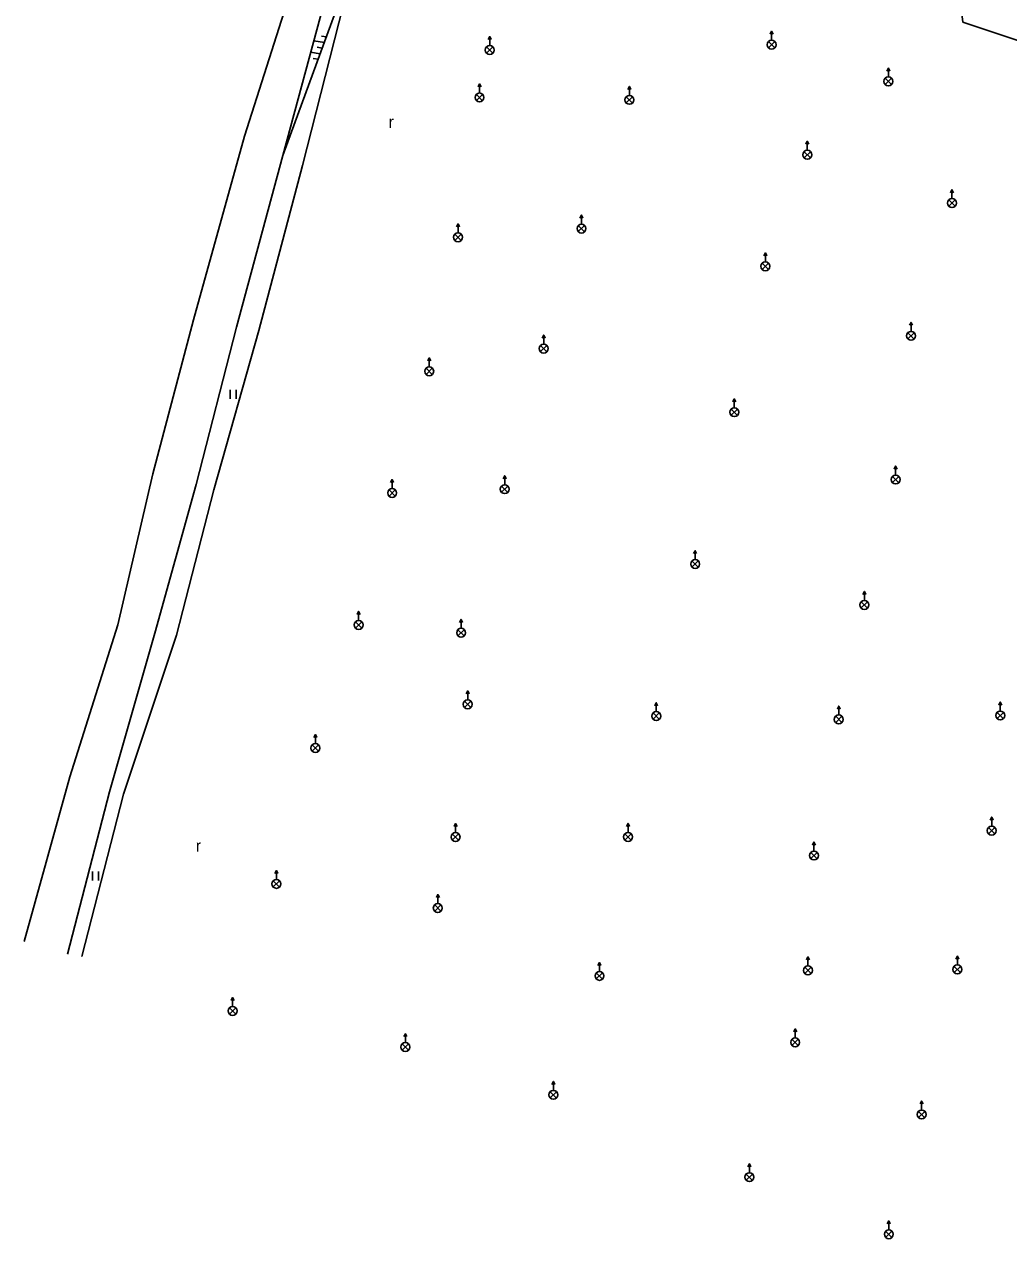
# Model space of a CAD drawing. Extents: x -639360 to -639196, y -1157339 to -1157085.
# Drawn here: x -639360.1 to -639277.4, y -1157292.9 to -1157191 of the extents above; entities that cross this region are included whole.
import ezdxf

# ---------------------------------------------------------------- set-up
doc = ezdxf.new("R2010")
doc.units = 0
for name, color, linetype in [('ROZHRANÍ_PLOCH', 7, 'Continuous'), ('VÝŠKOPIS', 7, 'Continuous'), ('ZELEŇ', 7, 'Continuous'), ('ZN_BP', 7, 'Continuous'), ('ZN_KULTUR', 7, 'Continuous')]:
    doc.layers.add(name, color=color, linetype=linetype)

msp = doc.modelspace()

# ---------------------------------------------------------------- linework, layer by layer
at = {"layer": 'ROZHRANÍ_PLOCH'}
for points in [[(-639331.83, -1157164.38), (-639335.16, -1157176.75), (-639337.86, -1157188.73), (-639341.57, -1157200.42), (-639345.86, -1157215.81), (-639349.27, -1157228.73), (-639352.21, -1157241.42), (-639356.25, -1157254.18), (-639360.06, -1157267.98)], [(-639328.42, -1157164.76), (-639330.23, -1157170.89), (-639331.87, -1157177.18), (-639334.88, -1157189.12), (-639338.37, -1157202.04), (-639342.24, -1157216.44), (-639345.64, -1157229.64), (-639349.1, -1157242.1), (-639352.92, -1157255.44), (-639356.43, -1157269.06)]]:
    msp.add_lwpolyline(points, dxfattribs=at)
at = {"layer": 'VÝŠKOPIS'}
for p, q in [((-639334.88, -1157192.55), (-639335.77, -1157192.41)), ((-639334.71, -1157192.08), (-639335.13, -1157192.01)), ((-639335.23, -1157193.49), (-639336.03, -1157193.36)), ((-639335.06, -1157193.02), (-639335.48, -1157192.95)), ((-639335.4, -1157193.96), (-639335.82, -1157193.89))]:
    msp.add_line(p, q, dxfattribs=at)
msp.add_lwpolyline([(-639321.87, -1157173.53), (-639324.78, -1157173.51), (-639327.96, -1157172.6), (-639329.05, -1157173.23), (-639330.82, -1157176.73), (-639333.63, -1157189.13), (-639338.37, -1157202.04)], dxfattribs=at)
at = {"layer": 'ZELEŇ'}
msp.add_lwpolyline([(-639263.89, -1157195.54), (-639272.49, -1157193.78), (-639281.29, -1157190.84), (-639281.78, -1157186.88), (-639294.17, -1157183.32), (-639306.87, -1157180.07), (-639317.99, -1157176.5), (-639324.82, -1157174.77), (-639328.28, -1157173.85), (-639329.62, -1157175.35), (-639333.27, -1157189.37), (-639336.7, -1157202.86), (-639340.39, -1157216.72), (-639344.16, -1157230.08), (-639347.28, -1157242.28), (-639351.74, -1157255.63), (-639355.24, -1157269.24)], dxfattribs=at)
at = {"layer": 'ZN_BP'}
for p, q in [((-639321, -1157192.8), (-639321, -1157192.05)), ((-639297.35, -1157192.35), (-639297.35, -1157191.6)), ((-639321.27, -1157193.44), (-639320.74, -1157192.92)), ((-639320.74, -1157193.45), (-639321.27, -1157192.92)), ((-639297.61, -1157192.99), (-639297.09, -1157192.47)), ((-639297.09, -1157193), (-639297.61, -1157192.47)), ((-639287.55, -1157195.44), (-639287.55, -1157194.69)), ((-639321.86, -1157196.78), (-639321.86, -1157196.03)), ((-639309.28, -1157196.99), (-639309.28, -1157196.24)), ((-639287.82, -1157196.07), (-639287.29, -1157195.55)), ((-639287.29, -1157196.08), (-639287.82, -1157195.55)), ((-639322.12, -1157197.42), (-639321.6, -1157196.9)), ((-639321.6, -1157197.43), (-639322.12, -1157196.9)), ((-639309.55, -1157197.62), (-639309.02, -1157197.1)), ((-639309.02, -1157197.63), (-639309.55, -1157197.1)), ((-639294.35, -1157201.59), (-639294.35, -1157200.84)), ((-639294.61, -1157202.23), (-639294.09, -1157201.71)), ((-639294.09, -1157202.24), (-639294.61, -1157201.71)), ((-639282.21, -1157205.65), (-639282.21, -1157204.9)), ((-639282.47, -1157206.28), (-639281.95, -1157205.76)), ((-639281.95, -1157206.29), (-639282.47, -1157205.76)), ((-639313.3, -1157207.78), (-639313.3, -1157207.03)), ((-639323.93, -1157209.15), (-639323.4, -1157208.63)), ((-639323.4, -1157209.16), (-639323.93, -1157208.63)), ((-639323.66, -1157208.52), (-639323.66, -1157207.77)), ((-639313.57, -1157208.42), (-639313.04, -1157207.9)), ((-639313.04, -1157208.43), (-639313.57, -1157207.9)), ((-639297.87, -1157210.96), (-639297.87, -1157210.21)), ((-639298.14, -1157211.59), (-639297.61, -1157211.07)), ((-639297.61, -1157211.6), (-639298.14, -1157211.07)), ((-639285.64, -1157216.78), (-639285.64, -1157216.03)), ((-639316.47, -1157217.85), (-639316.47, -1157217.1)), ((-639285.91, -1157217.42), (-639285.38, -1157216.9)), ((-639285.38, -1157217.43), (-639285.91, -1157216.9)), ((-639316.73, -1157218.49), (-639316.21, -1157217.97)), ((-639316.21, -1157218.5), (-639316.73, -1157217.97)), ((-639326.34, -1157220.4), (-639325.82, -1157219.88)), ((-639325.82, -1157220.41), (-639326.34, -1157219.88)), ((-639326.08, -1157219.77), (-639326.08, -1157219.02)), ((-639300.48, -1157223.2), (-639300.48, -1157222.45)), ((-639300.74, -1157223.83), (-639300.22, -1157223.31)), ((-639300.22, -1157223.84), (-639300.74, -1157223.31)), ((-639319.74, -1157229.66), (-639319.74, -1157228.91)), ((-639287.2, -1157229.48), (-639286.68, -1157228.96)), ((-639286.68, -1157229.49), (-639287.2, -1157228.96)), ((-639286.94, -1157228.84), (-639286.94, -1157228.09)), ((-639329.45, -1157230.61), (-639328.93, -1157230.09)), ((-639328.93, -1157230.62), (-639329.45, -1157230.09)), ((-639329.19, -1157229.98), (-639329.19, -1157229.23)), ((-639320.01, -1157230.29), (-639319.48, -1157229.77)), ((-639319.48, -1157230.3), (-639320.01, -1157229.77)), ((-639303.76, -1157235.94), (-639303.76, -1157235.19)), ((-639304.03, -1157236.57), (-639303.5, -1157236.05)), ((-639303.5, -1157236.58), (-639304.03, -1157236.05)), ((-639289.56, -1157239.36), (-639289.56, -1157238.61)), ((-639332, -1157241.04), (-639332, -1157240.29)), ((-639289.83, -1157240), (-639289.3, -1157239.48)), ((-639289.3, -1157240.01), (-639289.83, -1157239.48)), ((-639332.27, -1157241.68), (-639331.74, -1157241.16)), ((-639331.74, -1157241.69), (-639332.27, -1157241.16)), ((-639323.4, -1157241.71), (-639323.4, -1157240.96)), ((-639323.67, -1157242.34), (-639323.14, -1157241.82)), ((-639323.14, -1157242.35), (-639323.67, -1157241.82)), ((-639322.85, -1157247.71), (-639322.85, -1157246.96)), ((-639323.11, -1157248.34), (-639322.59, -1157247.82)), ((-639322.59, -1157248.35), (-639323.11, -1157247.82)), ((-639307.03, -1157248.7), (-639307.03, -1157247.95)), ((-639291.71, -1157248.98), (-639291.71, -1157248.23)), ((-639278.16, -1157248.65), (-639278.16, -1157247.9)), ((-639307.3, -1157249.33), (-639306.77, -1157248.81)), ((-639306.77, -1157249.34), (-639307.3, -1157248.81)), ((-639291.97, -1157249.61), (-639291.45, -1157249.09)), ((-639291.45, -1157249.62), (-639291.97, -1157249.09)), ((-639278.43, -1157249.28), (-639277.9, -1157248.76)), ((-639277.9, -1157249.29), (-639278.43, -1157248.76)), ((-639335.9, -1157252.01), (-639335.37, -1157251.49)), ((-639335.37, -1157252.02), (-639335.9, -1157251.49)), ((-639335.63, -1157251.38), (-639335.63, -1157250.62)), ((-639278.88, -1157258.3), (-639278.88, -1157257.55)), ((-639323.87, -1157258.84), (-639323.87, -1157258.09)), ((-639309.39, -1157258.83), (-639309.39, -1157258.08)), ((-639279.15, -1157258.94), (-639278.62, -1157258.42)), ((-639278.62, -1157258.95), (-639279.15, -1157258.42)), ((-639324.14, -1157259.48), (-639323.61, -1157258.96)), ((-639323.61, -1157259.49), (-639324.14, -1157258.96)), ((-639309.66, -1157259.47), (-639309.13, -1157258.95)), ((-639309.13, -1157259.48), (-639309.66, -1157258.95)), ((-639293.79, -1157260.4), (-639293.79, -1157259.65)), ((-639294.06, -1157261.03), (-639293.53, -1157260.51)), ((-639293.53, -1157261.04), (-639294.06, -1157260.51)), ((-639338.9, -1157262.78), (-639338.9, -1157262.03)), ((-639339.17, -1157263.41), (-639338.64, -1157262.89)), ((-639338.64, -1157263.42), (-639339.17, -1157262.89)), ((-639325.36, -1157264.8), (-639325.36, -1157264.05)), ((-639325.62, -1157265.44), (-639325.1, -1157264.92)), ((-639325.1, -1157265.45), (-639325.62, -1157264.92)), ((-639311.79, -1157270.5), (-639311.79, -1157269.75)), ((-639294.3, -1157270.03), (-639294.3, -1157269.28)), ((-639281.76, -1157269.96), (-639281.76, -1157269.21)), ((-639312.06, -1157271.13), (-639311.53, -1157270.61)), ((-639311.53, -1157271.14), (-639312.06, -1157270.61)), ((-639294.57, -1157270.67), (-639294.04, -1157270.15)), ((-639294.04, -1157270.68), (-639294.57, -1157270.15)), ((-639282.03, -1157270.59), (-639281.5, -1157270.07)), ((-639281.5, -1157270.6), (-639282.03, -1157270.07)), ((-639342.58, -1157273.44), (-639342.58, -1157272.69)), ((-639342.84, -1157274.07), (-639342.32, -1157273.55)), ((-639342.32, -1157274.08), (-639342.84, -1157273.55)), ((-639328.08, -1157276.47), (-639328.08, -1157275.72)), ((-639295.37, -1157276.07), (-639295.37, -1157275.32)), ((-639328.34, -1157277.1), (-639327.82, -1157276.58)), ((-639327.82, -1157277.11), (-639328.34, -1157276.58)), ((-639295.64, -1157276.71), (-639295.11, -1157276.19)), ((-639295.11, -1157276.72), (-639295.64, -1157276.19)), ((-639315.66, -1157280.48), (-639315.66, -1157279.73)), ((-639315.93, -1157281.11), (-639315.4, -1157280.59)), ((-639315.4, -1157281.12), (-639315.93, -1157280.59)), ((-639284.76, -1157282.12), (-639284.76, -1157281.38)), ((-639285.03, -1157282.76), (-639284.5, -1157282.24)), ((-639284.5, -1157282.77), (-639285.03, -1157282.24)), ((-639299.21, -1157287.39), (-639299.21, -1157286.64)), ((-639299.47, -1157288.02), (-639298.95, -1157287.5)), ((-639298.95, -1157288.03), (-639299.47, -1157287.5)), ((-639287.51, -1157292.18), (-639287.51, -1157291.43)), ((-639287.78, -1157292.81), (-639287.25, -1157292.29)), ((-639287.25, -1157292.82), (-639287.78, -1157292.29))]:
    msp.add_line(p, q, dxfattribs=at)
for points in [[(-639321.12, -1157192.3), (-639321, -1157192.05), (-639320.88, -1157192.3)], [(-639297.47, -1157191.85), (-639297.35, -1157191.6), (-639297.22, -1157191.85)], [(-639287.68, -1157194.94), (-639287.55, -1157194.69), (-639287.43, -1157194.94)], [(-639321.98, -1157196.28), (-639321.86, -1157196.03), (-639321.73, -1157196.28)], [(-639309.41, -1157196.49), (-639309.28, -1157196.24), (-639309.16, -1157196.49)], [(-639294.47, -1157201.09), (-639294.35, -1157200.84), (-639294.22, -1157201.09)], [(-639282.33, -1157205.15), (-639282.21, -1157204.9), (-639282.08, -1157205.15)], [(-639313.43, -1157207.28), (-639313.3, -1157207.03), (-639313.18, -1157207.28)], [(-639323.79, -1157208.02), (-639323.66, -1157207.77), (-639323.54, -1157208.02)], [(-639297.99, -1157210.46), (-639297.87, -1157210.21), (-639297.74, -1157210.46)], [(-639285.77, -1157216.28), (-639285.64, -1157216.03), (-639285.52, -1157216.28)], [(-639316.59, -1157217.35), (-639316.47, -1157217.1), (-639316.34, -1157217.35)], [(-639326.2, -1157219.27), (-639326.08, -1157219.02), (-639325.95, -1157219.27)], [(-639300.6, -1157222.7), (-639300.48, -1157222.45), (-639300.35, -1157222.7)], [(-639319.86, -1157229.16), (-639319.74, -1157228.91), (-639319.61, -1157229.16)], [(-639287.07, -1157228.34), (-639286.94, -1157228.09), (-639286.82, -1157228.34)], [(-639329.32, -1157229.48), (-639329.19, -1157229.23), (-639329.07, -1157229.48)], [(-639303.89, -1157235.44), (-639303.76, -1157235.19), (-639303.64, -1157235.44)], [(-639289.69, -1157238.86), (-639289.56, -1157238.61), (-639289.44, -1157238.86)], [(-639332.12, -1157240.54), (-639332, -1157240.29), (-639331.88, -1157240.54)], [(-639323.53, -1157241.21), (-639323.4, -1157240.96), (-639323.28, -1157241.21)], [(-639322.97, -1157247.21), (-639322.85, -1157246.96), (-639322.72, -1157247.21)], [(-639307.16, -1157248.2), (-639307.03, -1157247.95), (-639306.91, -1157248.2)], [(-639291.83, -1157248.48), (-639291.71, -1157248.23), (-639291.58, -1157248.48)], [(-639278.29, -1157248.15), (-639278.16, -1157247.9), (-639278.04, -1157248.15)], [(-639335.76, -1157250.88), (-639335.63, -1157250.62), (-639335.51, -1157250.88)], [(-639279.01, -1157257.8), (-639278.88, -1157257.55), (-639278.76, -1157257.8)], [(-639323.99, -1157258.34), (-639323.87, -1157258.09), (-639323.74, -1157258.34)], [(-639309.52, -1157258.33), (-639309.39, -1157258.08), (-639309.27, -1157258.33)], [(-639293.92, -1157259.9), (-639293.79, -1157259.65), (-639293.67, -1157259.9)], [(-639339.03, -1157262.28), (-639338.9, -1157262.03), (-639338.78, -1157262.28)], [(-639325.48, -1157264.3), (-639325.36, -1157264.05), (-639325.23, -1157264.3)], [(-639311.92, -1157270), (-639311.79, -1157269.75), (-639311.67, -1157270)], [(-639294.43, -1157269.53), (-639294.3, -1157269.28), (-639294.18, -1157269.53)], [(-639281.89, -1157269.46), (-639281.76, -1157269.21), (-639281.64, -1157269.46)], [(-639342.7, -1157272.94), (-639342.58, -1157272.69), (-639342.45, -1157272.94)], [(-639328.2, -1157275.97), (-639328.08, -1157275.72), (-639327.95, -1157275.97)], [(-639295.49, -1157275.57), (-639295.37, -1157275.32), (-639295.24, -1157275.57)], [(-639315.79, -1157279.98), (-639315.66, -1157279.73), (-639315.54, -1157279.98)], [(-639284.89, -1157281.62), (-639284.76, -1157281.38), (-639284.64, -1157281.62)], [(-639299.33, -1157286.89), (-639299.21, -1157286.64), (-639299.08, -1157286.89)], [(-639287.64, -1157291.68), (-639287.51, -1157291.43), (-639287.39, -1157291.68)]]:
    msp.add_lwpolyline(points, dxfattribs=at)
for centre in [(-639297.35, -1157192.73), (-639321, -1157193.18), (-639287.55, -1157195.81), (-639321.86, -1157197.16), (-639309.28, -1157197.36), (-639294.35, -1157201.97), (-639282.21, -1157206.02), (-639323.66, -1157208.89), (-639313.3, -1157208.16), (-639297.87, -1157211.33), (-639285.64, -1157217.16), (-639316.47, -1157218.23), (-639326.08, -1157220.14), (-639300.48, -1157223.57), (-639286.94, -1157229.22), (-639329.19, -1157230.35), (-639319.74, -1157230.03), (-639303.76, -1157236.31), (-639289.56, -1157239.74), (-639332, -1157241.42), (-639323.4, -1157242.08), (-639322.85, -1157248.08), (-639307.03, -1157249.07), (-639291.71, -1157249.35), (-639278.16, -1157249.02), (-639335.63, -1157251.75), (-639278.88, -1157258.68), (-639323.87, -1157259.22), (-639309.39, -1157259.21), (-639293.79, -1157260.77), (-639338.9, -1157263.15), (-639325.36, -1157265.18), (-639311.79, -1157270.87), (-639294.3, -1157270.41), (-639281.76, -1157270.33), (-639342.58, -1157273.81), (-639328.08, -1157276.84), (-639295.37, -1157276.45), (-639315.66, -1157280.85), (-639284.76, -1157282.5), (-639299.21, -1157287.76), (-639287.51, -1157292.55)]:
    msp.add_circle(centre, 0.375, dxfattribs=at)
at = {"layer": 'ZN_KULTUR'}
for p, q in [((-639342.78, -1157222.44), (-639342.78, -1157221.69)), ((-639342.28, -1157222.44), (-639342.28, -1157221.69)), ((-639354.34, -1157262.86), (-639354.34, -1157262.11)), ((-639353.84, -1157262.86), (-639353.84, -1157262.11))]:
    msp.add_line(p, q, dxfattribs=at)

# ---------------------------------------------------------------- texts
for p in [(-639329.49, -1157199.71), (-639345.67, -1157260.45)]:
    msp.add_text('r', height=1, dxfattribs=at).set_placement(p)

doc.saveas('drawing.dxf')
